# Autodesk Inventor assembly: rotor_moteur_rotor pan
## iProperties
Created: 2011-01
Part Number: rotor_moteur_rotor pan
Document SubType Name: Assembly
Designer: eric
Mass: 2.03418 g
Surface Area: 21.9258 cm^2
Volume: 2.03418 cm^3
Density: 1 g/cm^3
Norme de conversion: IGES 5.3
Nom du fichier: No Iges File Name specified
Préprocesseur: Autodesk Inventor 2011
Postprocesseur: Build: 342, Release: 2008 SP3 - Date: Tue 05/27/2008
Unités envoyées: MM
Incertitude: 0.01
Author: eric
